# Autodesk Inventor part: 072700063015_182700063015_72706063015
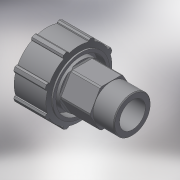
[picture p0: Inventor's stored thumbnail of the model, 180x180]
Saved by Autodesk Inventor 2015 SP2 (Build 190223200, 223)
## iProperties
Created: 2017-04
Part Number: 072700063015_182700063015_72706063015
Material: Generic
Description: PLASSON BRASS THREADED ADAPTOR 63-1.1/2"
Document SubType Name: Modeling
Designer: KIM
Density: 1 g/cm^3
Appearance: Default
Author: KIM
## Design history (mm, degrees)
derived "07270.ipt"
feature "Solid1::07270.ipt"
tag "TaggingFeature1"
body "Solid1"
other parameters: "d1" = 47.803, "d2" = 107, "d3" = 21, "d7" = 113, "d8" = 90.4, "d9" = 63, "d12" = 33.4621, "d13" = 38.2424, "d15" = 84.75, "d17" = 42.8, "d18" = 21, "d19" = 25.2, "d40" = 64, "d41" = 73.6, "d42" = 135 deg, "d43" = 100 deg, "d44" = 39.376, "d45" = 80.5125, "d46" = 105.09, "d47" = 35 deg, "d48" = 17.5 deg, "d50" = 0, "d52" = 360 deg, "d54" = 2.26, "d57" = 2.26, "d61" = 0, "d62" = 0.95606, "d65" = 1.43409, "d_" = 63, "R_" = 47.803, "E_" = 113, "H_" = 107, "l_2" = 21, "Wrench" = 64
